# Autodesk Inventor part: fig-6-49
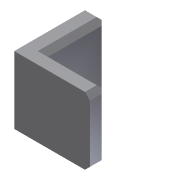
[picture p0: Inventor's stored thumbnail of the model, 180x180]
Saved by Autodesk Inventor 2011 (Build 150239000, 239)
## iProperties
Created: 2009-09
Part Number: fig-6-49
Document SubType Name: Modeling
Designer: Sham
Density: 1 g/cm^3
Author: Sham
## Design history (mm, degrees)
sketch "Sketch1"
  geometry: L1 (1.789, 30)-(1.789, -5); L2 (1.789, -5)-(36.789, -5); L3 (36.789, -5)-(36.789, -15); L4 (36.789, -15)-(-8.211, -15); L5 (-8.211, -15)-(-8.211, 30); L6 (-8.211, 30)-(1.789, 30)
  constraints: 12 end point, 6 perpendicular
  dimensions: "d0" = 10 distance of L5.end L1.start; "d1" = 35 distance of L1.start L1.end; "d2" = 45 distance of L3.end L4.end; "d3" = 10 distance of L2.end L3.end (derived)
extrude "Extrusion1" new body sketch "Sketch1" distance "d4" = 40; taper "d5" = 0 deg
chamfer "Chamfer1" distance "d6" = 3; stored, may be unused: second distance "d7" = 2, angle "d8" = 45 deg
body "Solid1"
other parameters: "d1" = 35
